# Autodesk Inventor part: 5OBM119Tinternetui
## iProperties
Created: 2010-11
Part Number: 5OBM119Tinternetui
Document SubType Name: Modeling
Designer: Darius
Author: Darius
Translation Standard: STEP AP203
File Name: 5OBM119T.STEP
Preprocessor: SolidWorks 2003240
Postprocessor: Build: 272, Release: 10 SP3a - Date: Thu 12/15/2005
Sent Units: MILLIMETERS
Uncertainty: 1e-05
